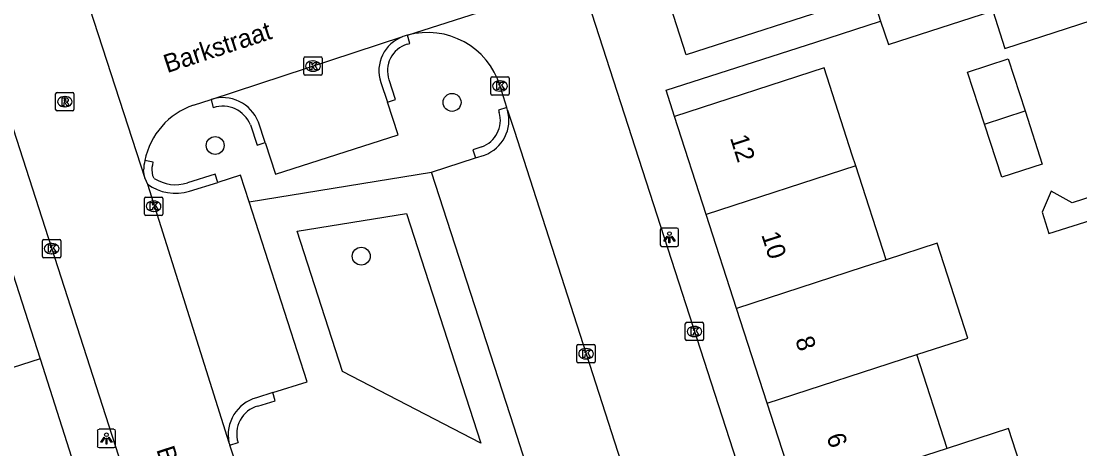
# Model space of a CAD drawing. Extents: x 159377 to 159983, y 382996 to 383595.
# Drawn here: x 159473.1 to 159530.9, y 383326.1 to 383349.4 of the extents above; entities that cross this region are included whole.
import ezdxf

# ---------------------------------------------------------------- set-up
doc = ezdxf.new("R2010")
doc.units = 0
for name, color, linetype in [('IMGEO_Boom', 7, 'Continuous'), ('IMGEO_Groenvoorziening', 7, 'Continuous'), ('IMGEO_Kolk', 7, 'Continuous'), ('IMGEO_Lichtpunt', 7, 'Continuous'), ('IMGEO_Muur', 7, 'Continuous'), ('IMGEO_Openbare_ruimte_label', 7, 'Continuous'), ('IMGEO_Pand', 7, 'Continuous'), ('IMGEO_Pand_nummerreeks', 7, 'Continuous'), ('IMGEO_Parkeervlak_open', 7, 'Continuous'), ('IMGEO_Rijbaan_lokaal_open', 7, 'Continuous'), ('IMGEO_Rioolput', 7, 'Continuous'), ('IMGEO_Voetpad_open', 7, 'Continuous')]:
    doc.layers.add(name, color=color, linetype=linetype)

msp = doc.modelspace()

# ---------------------------------------------------------------- linework, layer by layer
at = {"layer": 'IMGEO_Boom'}
for centre in [(159496.617, 383345.01), (159483.685, 383342.659), (159491.659, 383336.618)]:
    msp.add_circle(centre, 0.489, dxfattribs=at)
at = {"layer": 'IMGEO_Groenvoorziening'}
for points in [[(159485.541, 383339.58), (159495.497, 383341.203)], [(159490.629, 383330.329), (159488.159, 383337.981), (159494.123, 383338.953), (159498.18, 383326.423), (159490.629, 383330.329)]]:
    msp.add_lwpolyline(points, dxfattribs=at)
at = {"layer": 'IMGEO_Kolk'}
for p, q in [((159488.525, 383346.564), (159488.525, 383347.416)), ((159488.6, 383347.49), (159489.452, 383347.49)), ((159489.013, 383347.27), (159489.038, 383347.27)), ((159489.526, 383347.416), (159489.526, 383346.564)), ((159489.036, 383346.71), (159489.011, 383346.71)), ((159489.452, 383346.49), (159488.6, 383346.49)), ((159498.734, 383345.481), (159498.734, 383346.333)), ((159498.809, 383346.407), (159499.661, 383346.407)), ((159499.222, 383346.187), (159499.247, 383346.187)), ((159499.735, 383346.333), (159499.735, 383345.481)), ((159499.245, 383345.627), (159499.22, 383345.627)), ((159499.661, 383345.407), (159498.809, 383345.407)), ((159479.823, 383338.919), (159479.823, 383339.771)), ((159479.898, 383339.845), (159480.75, 383339.845)), ((159480.824, 383339.771), (159480.824, 383338.919)), ((159480.334, 383339.065), (159480.309, 383339.065)), ((159480.311, 383339.625), (159480.336, 383339.625)), ((159480.75, 383338.845), (159479.898, 383338.845)), ((159474.256, 383336.605), (159474.256, 383337.457)), ((159474.331, 383337.531), (159475.183, 383337.531)), ((159475.257, 383337.457), (159475.257, 383336.605)), ((159474.767, 383336.751), (159474.742, 383336.751)), ((159474.744, 383337.311), (159474.769, 383337.311)), ((159475.183, 383336.531), (159474.331, 383336.531)), ((159509.351, 383332.083), (159509.351, 383332.935)), ((159509.426, 383333.009), (159510.278, 383333.009)), ((159509.839, 383332.789), (159509.864, 383332.789)), ((159510.352, 383332.935), (159510.352, 383332.083)), ((159509.862, 383332.229), (159509.837, 383332.229)), ((159503.432, 383330.868), (159503.432, 383331.72)), ((159503.507, 383331.794), (159504.359, 383331.794)), ((159503.92, 383331.574), (159503.945, 383331.574)), ((159504.433, 383331.72), (159504.433, 383330.868)), ((159510.278, 383332.009), (159509.426, 383332.009)), ((159503.943, 383331.014), (159503.918, 383331.014)), ((159504.359, 383330.794), (159503.507, 383330.794))]:
    msp.add_line(p, q, dxfattribs=at)
for points in [[(159488.525, 383346.564), (159488.525, 383347.416)], [(159488.6, 383347.49), (159489.452, 383347.49)], [(159488.846, 383347.19), (159488.969, 383347.19), (159488.969, 383347.039), (159489.099, 383347.19), (159489.263, 383347.19), (159489.117, 383347.039), (159489.27, 383346.79), (159489.118, 383346.79), (159489.033, 383346.954), (159488.969, 383346.887), (159488.969, 383346.79), (159488.846, 383346.79), (159488.846, 383347.19)], [(159489.526, 383347.416), (159489.526, 383346.564)], [(159489.452, 383346.49), (159488.6, 383346.49)], [(159498.734, 383345.481), (159498.734, 383346.333)], [(159498.809, 383346.407), (159499.661, 383346.407)], [(159499.055, 383346.107), (159499.178, 383346.107), (159499.178, 383345.956), (159499.308, 383346.107), (159499.472, 383346.107), (159499.326, 383345.956), (159499.479, 383345.707), (159499.327, 383345.707), (159499.242, 383345.871), (159499.178, 383345.804), (159499.178, 383345.707), (159499.055, 383345.707), (159499.055, 383346.107)], [(159499.735, 383346.333), (159499.735, 383345.481)], [(159499.661, 383345.407), (159498.809, 383345.407)], [(159479.823, 383338.919), (159479.823, 383339.771)], [(159479.898, 383339.845), (159480.75, 383339.845)], [(159480.824, 383339.771), (159480.824, 383338.919)], [(159480.144, 383339.545), (159480.267, 383339.545), (159480.267, 383339.394), (159480.397, 383339.545), (159480.561, 383339.545), (159480.415, 383339.394), (159480.568, 383339.145), (159480.416, 383339.145), (159480.331, 383339.309), (159480.267, 383339.242), (159480.267, 383339.145), (159480.144, 383339.145), (159480.144, 383339.545)], [(159480.75, 383338.845), (159479.898, 383338.845)], [(159474.256, 383336.605), (159474.256, 383337.457)], [(159474.331, 383337.531), (159475.183, 383337.531)], [(159475.257, 383337.457), (159475.257, 383336.605)], [(159474.577, 383337.231), (159474.7, 383337.231), (159474.7, 383337.08), (159474.83, 383337.231), (159474.994, 383337.231), (159474.848, 383337.08), (159475.001, 383336.831), (159474.849, 383336.831), (159474.764, 383336.995), (159474.7, 383336.928), (159474.7, 383336.831), (159474.577, 383336.831), (159474.577, 383337.231)], [(159475.183, 383336.531), (159474.331, 383336.531)], [(159509.351, 383332.083), (159509.351, 383332.935)], [(159509.426, 383333.009), (159510.278, 383333.009)], [(159509.672, 383332.709), (159509.795, 383332.709), (159509.795, 383332.558), (159509.925, 383332.709), (159510.089, 383332.709), (159509.943, 383332.558), (159510.096, 383332.309), (159509.944, 383332.309), (159509.859, 383332.473), (159509.795, 383332.406), (159509.795, 383332.309), (159509.672, 383332.309), (159509.672, 383332.709)], [(159510.352, 383332.935), (159510.352, 383332.083)], [(159503.432, 383330.868), (159503.432, 383331.72)], [(159503.507, 383331.794), (159504.359, 383331.794)], [(159504.433, 383331.72), (159504.433, 383330.868)], [(159510.278, 383332.009), (159509.426, 383332.009)], [(159503.753, 383331.494), (159503.876, 383331.494), (159503.876, 383331.343), (159504.006, 383331.494), (159504.17, 383331.494), (159504.024, 383331.343), (159504.177, 383331.094), (159504.025, 383331.094), (159503.94, 383331.258), (159503.876, 383331.191), (159503.876, 383331.094), (159503.753, 383331.094), (159503.753, 383331.494)], [(159504.359, 383330.794), (159503.507, 383330.794)]]:
    msp.add_lwpolyline(points, dxfattribs=at)
for centre, start, end in [((159488.602, 383347.414), 91.55205, 178.44795), ((159488.602, 383347.414), 91.55205, 178.44795), ((159489.45, 383347.414), 1.55205, 88.44795), ((159489.45, 383347.414), 1.55205, 88.44795), ((159488.602, 383346.566), 181.55205, 268.44795), ((159488.602, 383346.566), 181.55205, 268.44795), ((159489.45, 383346.566), 271.55205, 358.44795), ((159489.45, 383346.566), 271.55205, 358.44795), ((159498.811, 383346.331), 91.55205, 178.44795), ((159498.811, 383346.331), 91.55205, 178.44795), ((159499.659, 383346.331), 1.55205, 88.44795), ((159499.659, 383346.331), 1.55205, 88.44795), ((159498.811, 383345.483), 181.55205, 268.44795), ((159498.811, 383345.483), 181.55205, 268.44795), ((159499.659, 383345.483), 271.55205, 358.44795), ((159499.659, 383345.483), 271.55205, 358.44795), ((159479.9, 383339.769), 91.55205, 178.44795), ((159479.9, 383339.769), 91.55205, 178.44795), ((159480.748, 383339.769), 1.55205, 88.44795), ((159480.748, 383339.769), 1.55205, 88.44795), ((159479.9, 383338.921), 181.55205, 268.44795), ((159479.9, 383338.921), 181.55205, 268.44795), ((159480.748, 383338.921), 271.55205, 358.44795), ((159480.748, 383338.921), 271.55205, 358.44795), ((159474.333, 383337.455), 91.55205, 178.44795), ((159474.333, 383337.455), 91.55205, 178.44795), ((159475.181, 383337.455), 1.55205, 88.44795), ((159475.181, 383337.455), 1.55205, 88.44795), ((159474.333, 383336.607), 181.55205, 268.44795), ((159474.333, 383336.607), 181.55205, 268.44795), ((159475.181, 383336.607), 271.55205, 358.44795), ((159475.181, 383336.607), 271.55205, 358.44795), ((159509.428, 383332.933), 91.55205, 178.44795), ((159509.428, 383332.933), 91.55205, 178.44795), ((159510.276, 383332.933), 1.55205, 88.44795), ((159510.276, 383332.933), 1.55205, 88.44795), ((159503.509, 383331.718), 91.55205, 178.44795), ((159503.509, 383331.718), 91.55205, 178.44795), ((159504.357, 383331.718), 1.55205, 88.44795), ((159504.357, 383331.718), 1.55205, 88.44795), ((159509.428, 383332.085), 181.55205, 268.44795), ((159509.428, 383332.085), 181.55205, 268.44795), ((159510.276, 383332.085), 271.55205, 358.44795), ((159510.276, 383332.085), 271.55205, 358.44795), ((159503.509, 383330.87), 181.55205, 268.44795), ((159503.509, 383330.87), 181.55205, 268.44795), ((159504.357, 383330.87), 271.55205, 358.44795), ((159504.357, 383330.87), 271.55205, 358.44795)]:
    msp.add_arc(centre, 0.0765, start, end, dxfattribs=at)
for centre, major_axis, ratio, start_param, end_param in [((159489.012, 383346.99), (-0.387, 0.002), 0.722429, 4.712389, 7.853982), ((159489.037, 383346.99), (-0.39, 0.002), 0.717154, 1.570796, 4.712389), ((159499.221, 383345.907), (-0.387, 0.002), 0.722429, 4.712389, 7.853982), ((159499.246, 383345.907), (-0.39, 0.002), 0.717154, 1.570796, 4.712389), ((159480.31, 383339.345), (-0.387, 0.002), 0.722429, 4.712389, 7.853982), ((159480.335, 383339.345), (-0.39, 0.002), 0.717154, 1.570796, 4.712389), ((159474.743, 383337.031), (-0.387, 0.002), 0.722429, 4.712389, 7.853982), ((159474.768, 383337.031), (-0.39, 0.002), 0.717154, 1.570796, 4.712389), ((159509.838, 383332.509), (-0.387, 0.002), 0.722429, 4.712389, 7.853982), ((159509.863, 383332.509), (-0.39, 0.002), 0.717154, 1.570796, 4.712389), ((159503.919, 383331.294), (-0.387, 0.002), 0.722429, 4.712389, 7.853982), ((159503.944, 383331.294), (-0.39, 0.002), 0.717154, 1.570796, 4.712389)]:
    msp.add_ellipse(centre, major_axis=major_axis, ratio=ratio, start_param=start_param, end_param=end_param, dxfattribs=at)
at = {"layer": 'IMGEO_Lichtpunt'}
for p, q in [((159507.986, 383338.053), (159507.986, 383337.246)), ((159507.986, 383338.053), (159507.986, 383337.246)), ((159508.888, 383338.148), (159508.08, 383338.148)), ((159508.888, 383338.148), (159508.08, 383338.148)), ((159508.982, 383337.246), (159508.982, 383338.053)), ((159508.982, 383337.246), (159508.982, 383338.053)), ((159508.08, 383337.152), (159508.888, 383337.152)), ((159508.08, 383337.152), (159508.888, 383337.152)), ((159477.251, 383327.074), (159477.251, 383326.267)), ((159477.251, 383327.074), (159477.251, 383326.267)), ((159478.153, 383327.169), (159477.345, 383327.169)), ((159478.153, 383327.169), (159477.345, 383327.169)), ((159478.247, 383326.267), (159478.247, 383327.074)), ((159478.247, 383326.267), (159478.247, 383327.074)), ((159477.345, 383326.173), (159478.153, 383326.173)), ((159477.345, 383326.173), (159478.153, 383326.173))]:
    msp.add_line(p, q, dxfattribs=at)
for points in [[(159508.36, 383337.717), (159508.399, 383337.689), (159508.211, 383337.427), (159508.173, 383337.454), (159508.36, 383337.717)], [(159508.462, 383337.669), (159508.509, 383337.669), (159508.509, 383337.347), (159508.462, 383337.347), (159508.462, 383337.669)], [(159508.572, 383337.689), (159508.61, 383337.716), (159508.797, 383337.454), (159508.758, 383337.426), (159508.572, 383337.689)], [(159477.625, 383326.738), (159477.664, 383326.71), (159477.476, 383326.448), (159477.438, 383326.475), (159477.625, 383326.738)], [(159477.727, 383326.69), (159477.774, 383326.69), (159477.774, 383326.368), (159477.727, 383326.368), (159477.727, 383326.69)], [(159477.837, 383326.71), (159477.875, 383326.737), (159478.062, 383326.475), (159478.023, 383326.447), (159477.837, 383326.71)]]:
    msp.add_lwpolyline(points, dxfattribs=at)
for centre in [(159508.485, 383337.851), (159477.75, 383326.872)]:
    msp.add_circle(centre, 0.0994, dxfattribs=at)
for centre, start, end in [((159508.08, 383338.053), 90, 180), ((159508.08, 383338.053), 90, 180), ((159508.888, 383338.053), 0, 90), ((159508.888, 383338.053), 0, 90), ((159508.08, 383337.246), 180, 270), ((159508.08, 383337.246), 180, 270), ((159508.888, 383337.246), 270, 0), ((159508.888, 383337.246), 270, 360), ((159477.345, 383327.074), 90, 180), ((159477.345, 383327.074), 90, 180), ((159478.153, 383327.074), 0, 90), ((159478.153, 383327.074), 0, 90), ((159477.345, 383326.267), 180, 270), ((159477.345, 383326.267), 180, 270), ((159478.153, 383326.267), 270, 0), ((159478.153, 383326.267), 270, 360)]:
    msp.add_arc(centre, 0.0946, start, end, dxfattribs=at)
at = {"layer": 'IMGEO_Muur'}
msp.add_lwpolyline([(159516.472, 383348.302), (159520.015, 383349.441)], dxfattribs=at)
at = {"layer": 'IMGEO_Pand'}
for points in [[(159526.135, 383350.002), (159526.801, 383347.947), (159531.558, 383349.489), (159532.3, 383349.729), (159530.411, 383355.56)], [(159525.689, 383343.823), (159524.767, 383346.668), (159526.983, 383347.386), (159527.905, 383344.541)], [(159518.657, 383341.545), (159518.467, 383342.131), (159516.929, 383346.888), (159508.756, 383344.243)], [(159527.905, 383344.541), (159528.845, 383341.64), (159526.629, 383340.922), (159525.689, 383343.823)], [(159525.689, 383343.823), (159527.905, 383344.541)], [(159510.485, 383338.898), (159508.756, 383344.243)], [(159518.657, 383341.545), (159510.485, 383338.898)], [(159520.315, 383336.416), (159518.657, 383341.545)], [(159512.144, 383333.769), (159510.485, 383338.898)], [(159521.986, 383331.247), (159524.784, 383332.153), (159523.11, 383337.322), (159520.315, 383336.416)], [(159472.472, 383336.172), (159474.127, 383331.019)], [(159520.315, 383336.416), (159519.067, 383336.012), (159512.144, 383333.769)], [(159513.815, 383328.601), (159512.144, 383333.769)], [(159474.127, 383331.019), (159465.962, 383328.388)], [(159474.127, 383331.019), (159475.849, 383325.659)], [(159513.815, 383328.601), (159521.986, 383331.247)], [(159523.642, 383326.126), (159521.986, 383331.247)], [(159515.471, 383323.48), (159513.815, 383328.601)], [(159525.31, 383320.968), (159528.664, 383322.054), (159526.996, 383327.212), (159523.642, 383326.126)], [(159523.642, 383326.126), (159515.471, 383323.48)]]:
    msp.add_lwpolyline(points, dxfattribs=at)
at = {"layer": 'IMGEO_Parkeervlak_open'}
for points in [[(159486.415, 383342.814), (159486.984, 383341.088), (159493.677, 383343.248), (159493.089, 383345.024)], [(159495.497, 383341.203), (159497.889, 383341.976)], [(159485.541, 383339.58), (159485.072, 383341.032), (159483.826, 383340.644)], [(159501.334, 383323.171), (159500.626, 383325.36), (159500, 383327.293), (159495.497, 383341.203)], [(159486.828, 383329.174), (159488.71, 383329.763), (159485.541, 383339.58)]]:
    msp.add_lwpolyline(points, dxfattribs=at)
at = {"layer": 'IMGEO_Rijbaan_lokaal_open'}
for points in [[(159462.363, 383367.551), (159464.643, 383368.374), (159482.73, 383312.288)], [(159517.861, 383356.203), (159520.015, 383349.441)], [(159476.124, 383352.314), (159479.838, 383340.87)], [(159494.182, 383348.675), (159503.646, 383351.717)], [(159503.646, 383351.717), (159513.324, 383321.769)], [(159520.015, 383349.441), (159520.44, 383348.178), (159526.135, 383350.002)], [(159483.466, 383345.171), (159493.936, 383348.598)], [(159499.601, 383344.723), (159499.237, 383345.904)], [(159482.492, 383344.854), (159483.466, 383345.171)], [(159499.642, 383344.595), (159499.601, 383344.723)], [(159499.642, 383344.595), (159500, 383343.486), (159507.545, 383320.103)], [(159479.838, 383340.87), (159479.77, 383341.31)], [(159479.838, 383340.87), (159479.991, 383340.549)], [(159479.991, 383340.549), (159484.434, 383326.453)], [(159484.434, 383326.453), (159484.484, 383326.299)], [(159485.755, 383322.408), (159485.48, 383323.262), (159484.484, 383326.299)]]:
    msp.add_lwpolyline(points, dxfattribs=at)
for centre, radius, start, end in [((159495.493, 383344.056), 4.801, 105.84226, 108.91883), ((159495.287, 383344.694), 4.131, 17.02557, 105.51396), ((159483.788, 383341.041), 4.027, 108.77114, 168.54274), ((159483.925, 383341.025), 4.164, 168.69616, 176.07215)]:
    msp.add_arc(centre, radius, start, end, dxfattribs=at)
at = {"layer": 'IMGEO_Rioolput'}
for p, q in [((159474.975, 383344.622), (159474.975, 383345.474)), ((159475.05, 383345.548), (159475.902, 383345.548)), ((159475.976, 383345.474), (159475.976, 383344.622)), ((159475.463, 383345.328), (159475.488, 383345.328)), ((159475.902, 383344.548), (159475.05, 383344.548)), ((159475.486, 383344.768), (159475.461, 383344.768))]:
    msp.add_line(p, q, dxfattribs=at)
for points in [[(159474.975, 383344.622), (159474.975, 383345.474)], [(159475.05, 383345.548), (159475.902, 383345.548)], [(159475.976, 383345.474), (159475.976, 383344.622)], [(159475.564, 383345.246), (159475.312, 383345.248), (159475.312, 383344.848)], [(159475.312, 383344.848), (159475.436, 383344.848), (159475.436, 383345.01), (159475.447, 383345.01)], [(159475.49, 383345.167), (159475.436, 383345.167), (159475.436, 383345.086)], [(159475.436, 383345.086), (159475.488, 383345.086)], [(159475.494, 383344.981), (159475.565, 383344.848), (159475.705, 383344.848), (159475.64, 383344.974)], [(159475.902, 383344.548), (159475.05, 383344.548)]]:
    msp.add_lwpolyline(points, dxfattribs=at)
for centre, radius, start, end in [((159475.052, 383345.472), 0.0765, 91.55205, 178.44795), ((159475.052, 383345.472), 0.0765, 91.55205, 178.44795), ((159475.9, 383345.472), 0.0765, 1.55205, 88.44795), ((159475.9, 383345.472), 0.0765, 1.55205, 88.44795), ((159475.446, 383344.957), 0.0533, 26.02933, 88.69889), ((159475.472, 383345.275), 0.19, 274.7715, 282.96867), ((159475.496, 383345.071), 0.0964, 77.00612, 93.18647), ((159475.51, 383345.128), 0.0378, 276.66336, 79.67722), ((159475.563, 383345.136), 0.109, 350.36119, 89.41601), ((159475.561, 383345.136), 0.112, 277.58423, 350.98172), ((159475.545, 383344.921), 0.108, 29.51342, 73.79051), ((159475.052, 383344.624), 0.0765, 181.55205, 268.44795), ((159475.052, 383344.624), 0.0765, 181.55205, 268.44795), ((159475.9, 383344.624), 0.0765, 271.55205, 358.44795), ((159475.9, 383344.624), 0.0765, 271.55205, 358.44795)]:
    msp.add_arc(centre, radius, start, end, dxfattribs=at)
for centre, major_axis, ratio, start_param, end_param in [((159475.462, 383345.048), (-0.387, 0.002), 0.722429, 4.712389, 7.853982), ((159475.487, 383345.048), (-0.39, 0.002), 0.717154, 1.570796, 4.712389)]:
    msp.add_ellipse(centre, major_axis=major_axis, ratio=ratio, start_param=start_param, end_param=end_param, dxfattribs=at)
at = {"layer": 'IMGEO_Voetpad_open'}
for points in [[(159517.054, 383354.822), (159518.443, 383350.513), (159509.407, 383347.607), (159508.192, 383351.347)], [(159508.756, 383344.243), (159508.306, 383345.678), (159516.472, 383348.302), (159520.015, 383349.441)], [(159494.162, 383348.182), (159494.307, 383348.225), (159494.182, 383348.675)], [(159492.733, 383346.099), (159493.089, 383345.024)], [(159493.089, 383345.024), (159493.532, 383345.171), (159493.175, 383346.249)], [(159483.466, 383345.171), (159483.583, 383344.719)], [(159499.601, 383344.723), (159499.156, 383344.583), (159499.196, 383344.46)], [(159485.606, 383343.777), (159485.972, 383342.668), (159486.415, 383342.814)], [(159486.415, 383342.814), (159486.045, 383343.935)], [(159498.235, 383342.578), (159497.745, 383342.42), (159497.889, 383341.976)], [(159497.889, 383341.976), (159498.387, 383342.137)], [(159480.358, 383340.862), (159480.288, 383341.009), (159480.239, 383341.329), (159480.253, 383341.469), (159480.273, 383341.609), (159480.298, 383341.748), (159479.841, 383341.841)], [(159537.659, 383339.372), (159536.895, 383341.602), (159530.48, 383339.535), (159529.324, 383340.162), (159528.831, 383339.018), (159529.193, 383337.862), (159535.841, 383339.945), (159536.166, 383338.907)], [(159483.826, 383340.644), (159483.687, 383341.089), (159482.176, 383340.618)], [(159482.281, 383340.162), (159483.826, 383340.644)], [(159486.828, 383329.174), (159485.936, 383328.895)], [(159486.014, 383328.439), (159486.966, 383328.732), (159486.828, 383329.174)], [(159484.484, 383326.299), (159484.933, 383326.446)]]:
    msp.add_lwpolyline(points, dxfattribs=at)
for centre, radius, start, end in [((159494.595, 383346.742), 1.97, 109.53932, 199.04904), ((159494.593, 383346.744), 1.502, 106.67403, 199.22777), ((159484.098, 383343.181), 2.088, 21.171, 107.61634), ((159484.1, 383343.185), 1.619, 21.45127, 108.61111), ((159497.695, 383344.04), 1.559, 290.26678, 15.63305), ((159497.697, 383344.038), 2.023, 289.93341, 15.9709), ((159481.524, 383342.657), 2.14, 236.98437, 287.72726), ((159481.524, 383342.652), 2.603, 233.91138, 286.9044), ((159486.501, 383326.865), 2.108, 105.55144, 191.25974), ((159486.428, 383326.925), 1.57, 105.29833, 197.751)]:
    msp.add_arc(centre, radius, start, end, dxfattribs=at)

# ---------------------------------------------------------------- texts
at = {"layer": 'IMGEO_Openbare_ruimte_label'}
for s, rotation, p in [('Barkstraat', 18.12681, (159481.064, 383346.606)), ('Boegstraat', 288.18127, (159480.461, 383326.065))]:
    msp.add_text(s, height=1, rotation=rotation, dxfattribs=at).set_placement(p)
at = {"layer": 'IMGEO_Pand_nummerreeks'}
for s, rotation, p in [('12', 287.92277, (159511.782, 383343.078)), ('10', 287.92277, (159513.492, 383337.789)), ('8', 287.92191, (159515.343, 383332.065)), ('6', 287.92277, (159517.05, 383326.785))]:
    msp.add_text(s, height=1, rotation=rotation, dxfattribs=at).set_placement(p)

doc.saveas('drawing.dxf')
